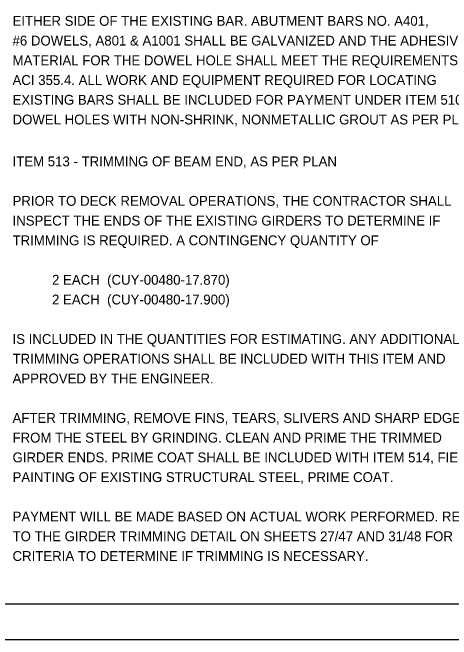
# Model space of a CAD drawing. Extents: x 0 to 34, y 0 to 22.
# Drawn here: x 24.66 to 30.88, y 0 to 8.9 of the extents above; entities that cross this region are included whole.
import ezdxf

# ---------------------------------------------------------------- set-up
doc = ezdxf.new("R2010")
doc.units = 0
for name, color, linetype in [('SH_Border', 7, 'Continuous'), ('SH_Cut_Line', 7, 'Continuous'), ('SH_Text', 7, 'Continuous')]:
    doc.layers.add(name, color=color, linetype=linetype)

msp = doc.modelspace()

# ---------------------------------------------------------------- linework, layer by layer
at = {"layer": 'SH_Border'}
msp.add_lwpolyline([(1.5, 21.5), (33.5, 21.5), (33.5, 0.5), (1.5, 0.5)], close=True, dxfattribs=at)
at = {"layer": 'SH_Cut_Line'}
msp.add_lwpolyline([(0, 0), (34, 0), (34, 22), (0, 22)], close=True, dxfattribs=at)

# ---------------------------------------------------------------- texts
at = {"layer": 'SH_Text'}
for s, p in [('EITHER SIDE OF THE EXISTING BAR. ABUTMENT BARS NO. A401, ', (24.66, 8.7087)), ('#6 DOWELS, A801 & A1001 SHALL BE GALVANIZED AND THE ADHESIVE ', (24.66, 8.4287)), ('MATERIAL FOR THE DOWEL HOLE SHALL MEET THE REQUIREMENTS OF ', (24.66, 8.1487)), ('ACI 355.4. ALL WORK AND EQUIPMENT REQUIRED FOR LOCATING ', (24.66, 7.8687)), ('EXISTING BARS SHALL BE INCLUDED FOR PAYMENT UNDER ITEM 510, ', (24.66, 7.5887)), ('DOWEL HOLES WITH NON-SHRINK, NONMETALLIC GROUT AS PER PLAN.', (24.66, 7.3087)), ('ITEM 513 - TRIMMING OF BEAM END, AS PER PLAN', (24.66, 6.7141)), ('PRIOR TO DECK REMOVAL OPERATIONS, THE CONTRACTOR SHALL ', (24.66, 6.1541)), ('INSPECT THE ENDS OF THE EXISTING GIRDERS TO DETERMINE IF ', (24.66, 5.8741)), ('TRIMMING IS REQUIRED. A CONTINGENCY QUANTITY OF', (24.66, 5.5941)), ('2 EACH  (CUY-00480-17.870)', (25.22, 5.0341)), ('2 EACH  (CUY-00480-17.900)', (25.22, 4.7541)), ('IS INCLUDED IN THE QUANTITIES FOR ESTIMATING. ANY ADDITIONAL ', (24.66, 4.1941)), ('TRIMMING OPERATIONS SHALL BE INCLUDED WITH THIS ITEM AND ', (24.66, 3.9141)), ('APPROVED BY THE ENGINEER.', (24.66, 3.6341)), ('AFTER TRIMMING, REMOVE FINS, TEARS, SLIVERS AND SHARP EDGES ', (24.66, 3.0741)), ('FROM THE STEEL BY GRINDING. CLEAN AND PRIME THE TRIMMED ', (24.66, 2.7941)), ('GIRDER ENDS. PRIME COAT SHALL BE INCLUDED WITH ITEM 514, FIELD ', (24.66, 2.5141)), ('PAINTING OF EXISTING STRUCTURAL STEEL, PRIME COAT.', (24.66, 2.2341)), ('PAYMENT WILL BE MADE BASED ON ACTUAL WORK PERFORMED. REFER ', (24.66, 1.6741)), ('TO THE GIRDER TRIMMING DETAIL ON SHEETS 27/47 AND 31/48 FOR ', (24.66, 1.3941)), ('CRITERIA TO DETERMINE IF TRIMMING IS NECESSARY.', (24.66, 1.1141))]:
    msp.add_text(s, height=0.14, dxfattribs=at).set_placement(p)

doc.saveas('drawing.dxf')
